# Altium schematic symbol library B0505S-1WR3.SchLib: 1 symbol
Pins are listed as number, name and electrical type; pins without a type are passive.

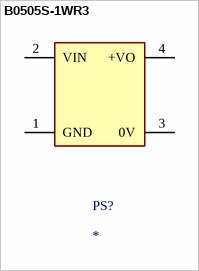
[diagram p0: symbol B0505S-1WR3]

## B0505S-1WR3
designator PS?
Isolated Module DC DC Converter 1 Output 5V 200mA 4.5V - 5.5V Input; MF: Mornsun America, LLC; MP: B0505S-1WR3
footprint B0503S-1W
pins: 1 GND (power), 2 VIN (power), 3 0V (power), 4 +VO (power)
